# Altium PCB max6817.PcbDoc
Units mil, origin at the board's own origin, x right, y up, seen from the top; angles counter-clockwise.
Board outline 6000 x 4000 mil, 2 copper layers (Top Layer, Bottom Layer); 13 components, 8 nets, 32 pads, 2 vias.
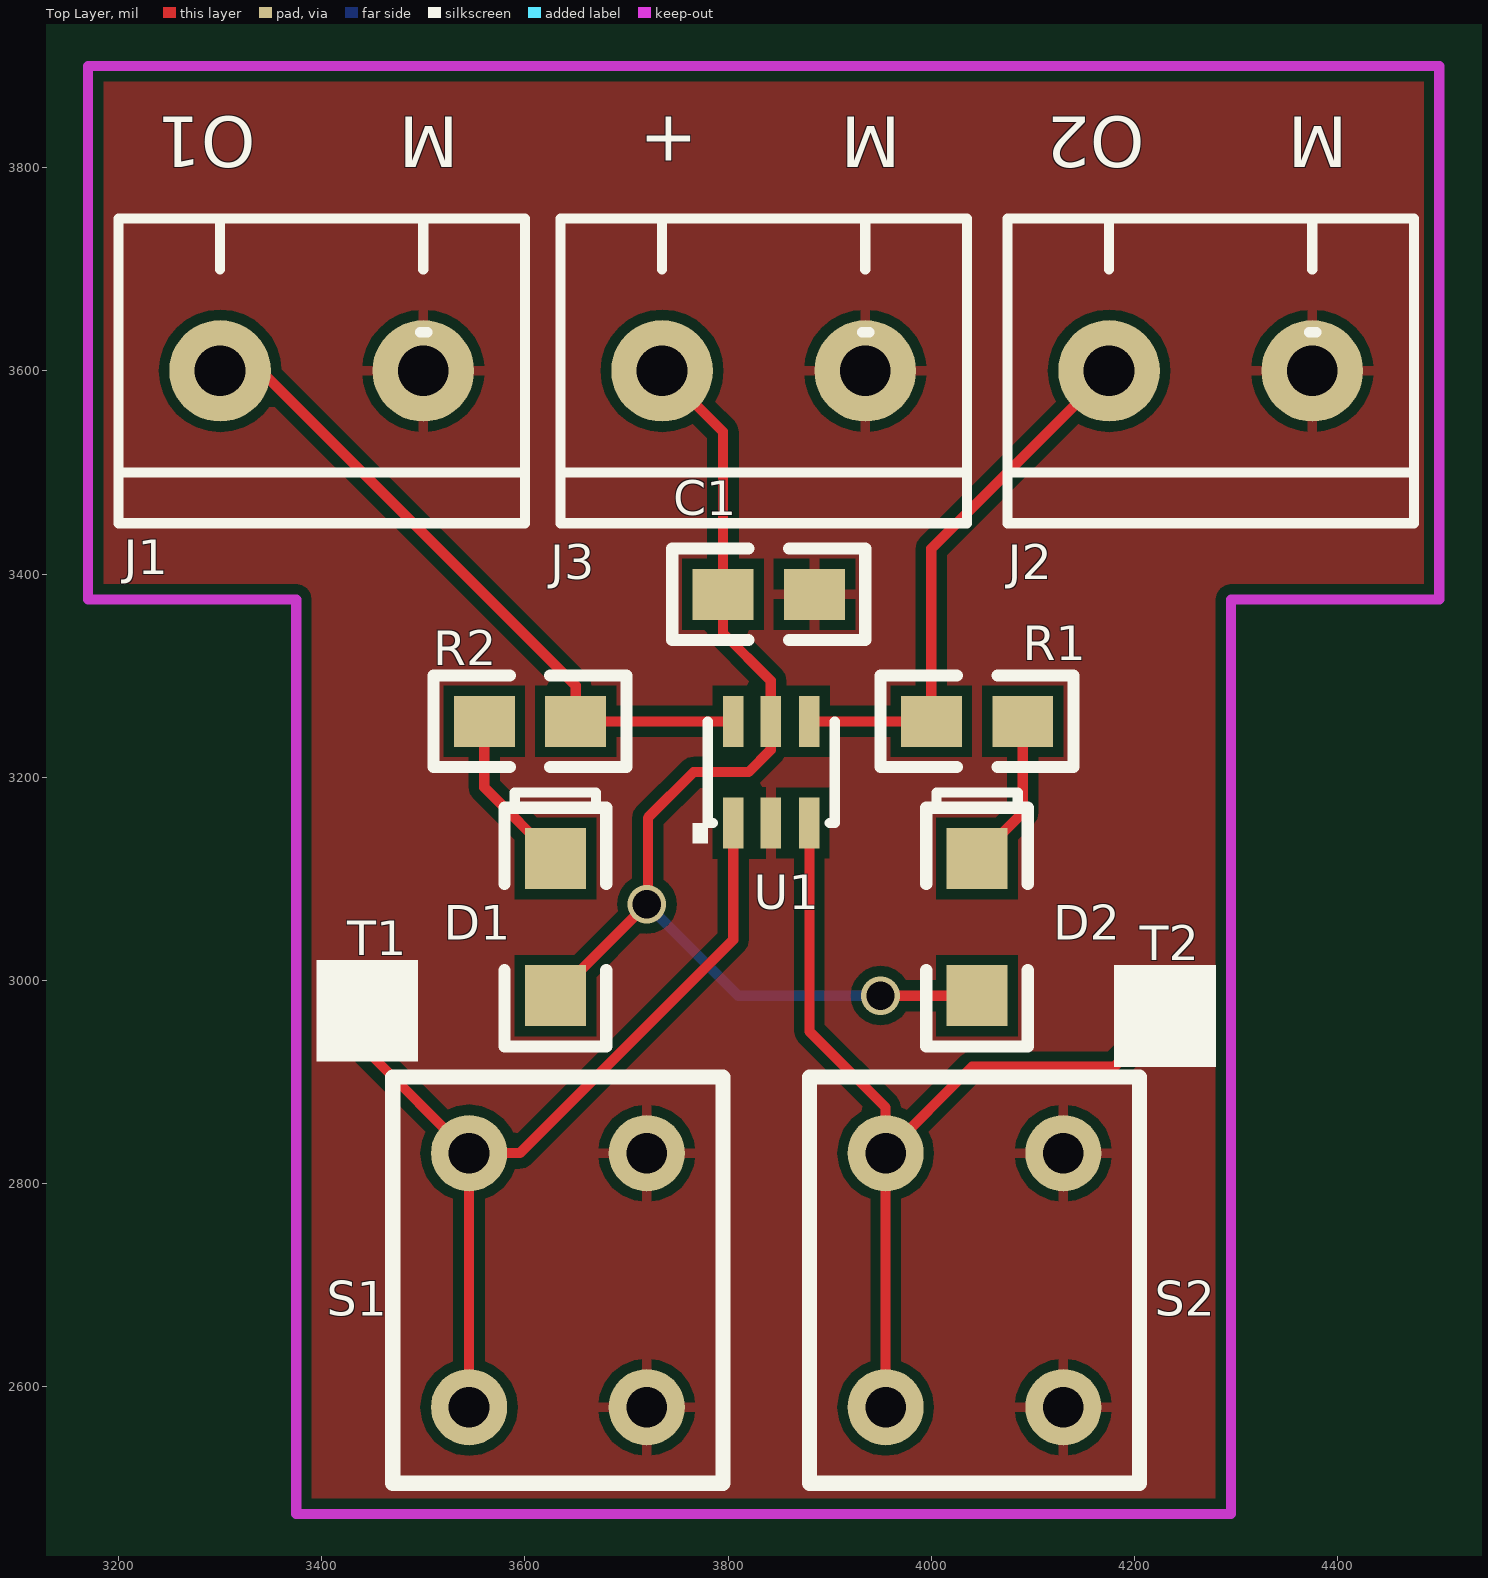
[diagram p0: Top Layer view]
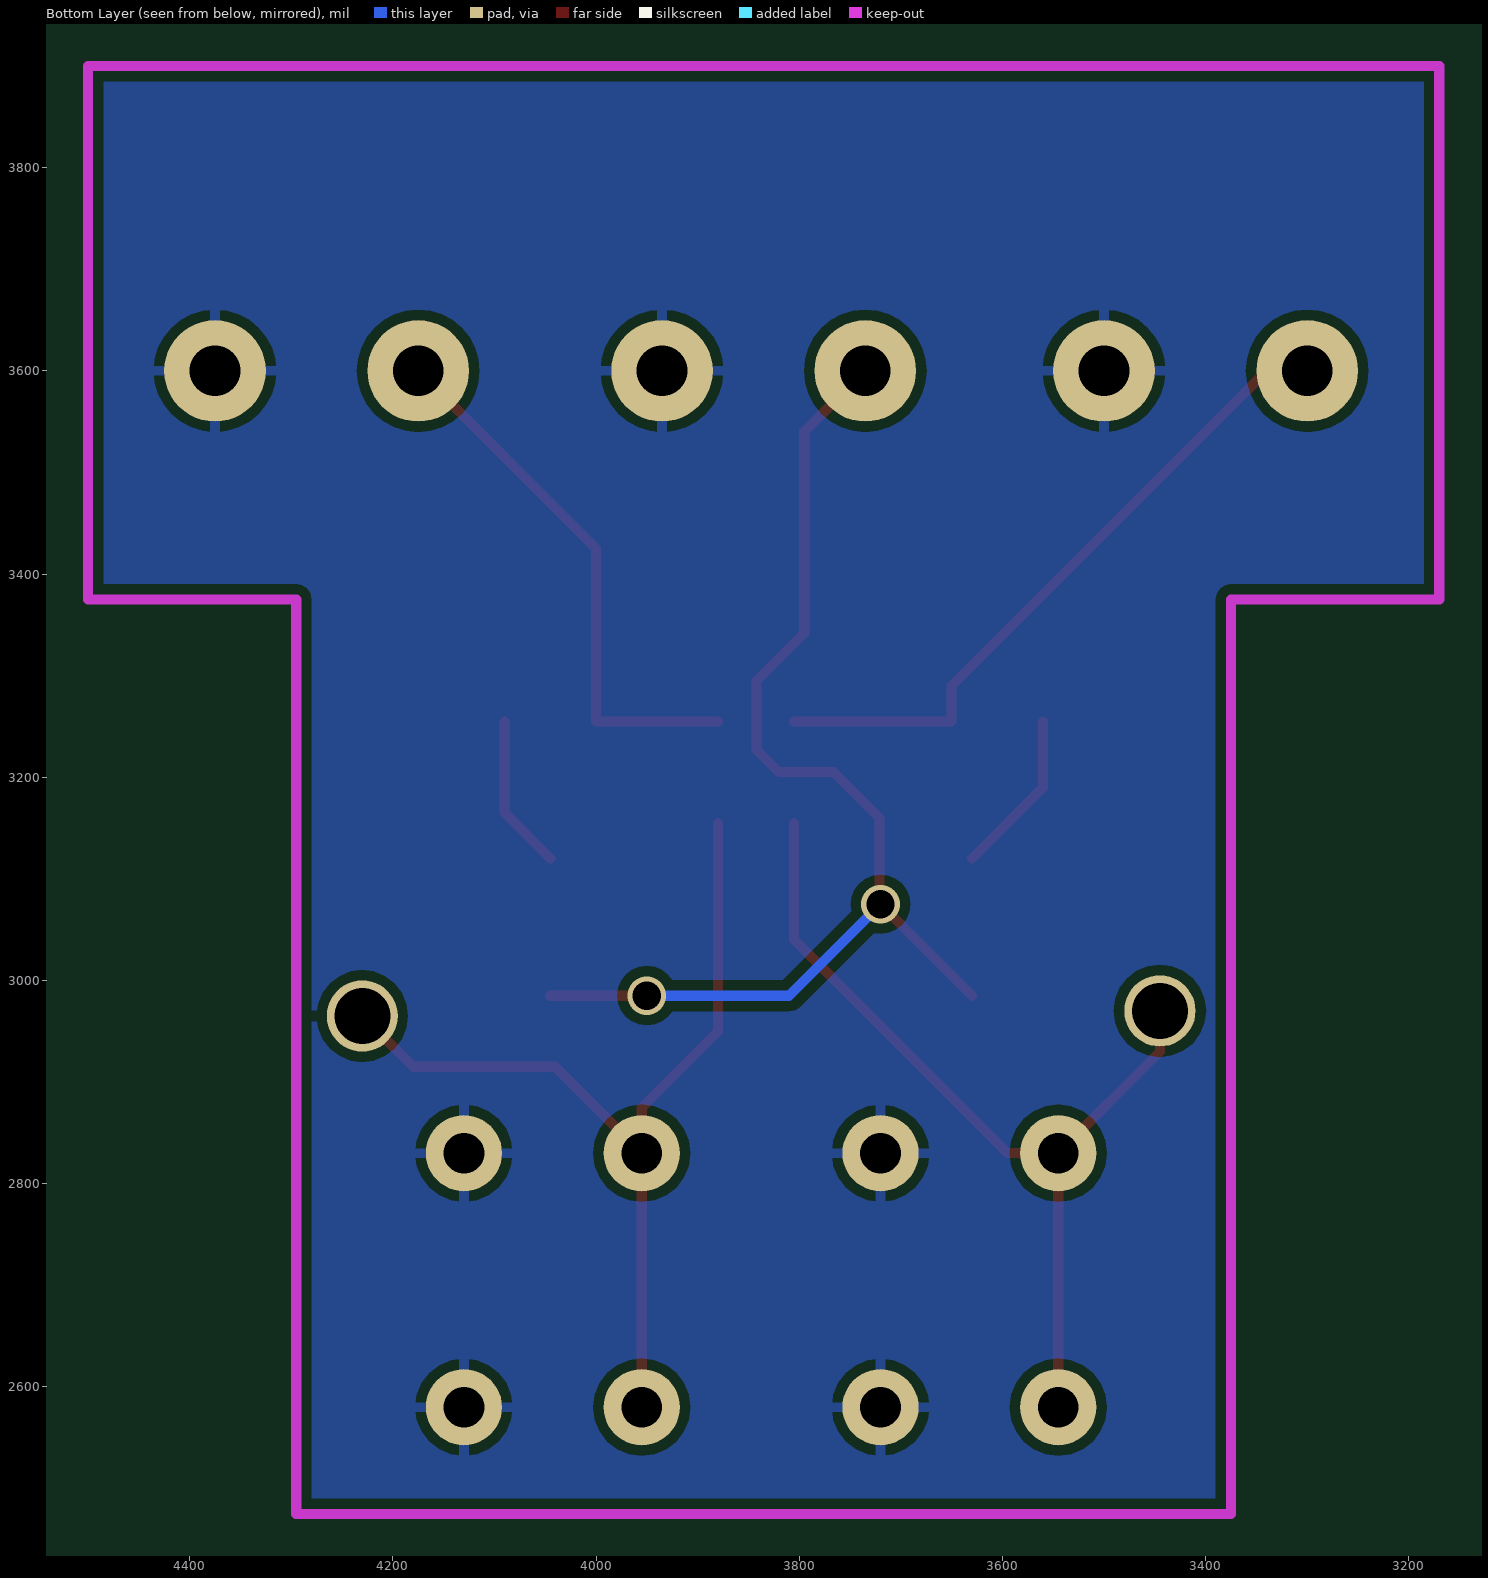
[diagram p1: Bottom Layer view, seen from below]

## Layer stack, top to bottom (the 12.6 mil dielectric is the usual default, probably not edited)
Top Layer: signal copper 1.4
Dielectric: dielectric 12.6, FR-4, Dk 4.8
Bottom Layer: signal copper 1.4

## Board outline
1000,1000 7000,1000 7000,5000 1000,5000

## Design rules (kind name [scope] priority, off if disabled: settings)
Clearance [All] p1: gap=10
PolygonConnect [All] p1: connectstyle=Relief reliefconductorwidth=10 reliefentries=4 polygonreliefangle="90 Angle"
RoutingVias [All] p1: holewidth=28 width=50 viastyle="Through Hole" minholewidth=28 minwidth=50 maxholewidth=28 maxwidth=50
SilkscreenOverComponentPads [All] p1: minsilkscreentomaskgap=10
SolderMaskExpansion [All] p1: expansion=4
Width [All] p1: maxlimit=10 minlimit=10 preferedwidth=10
27 further rules are at their usual default settings.

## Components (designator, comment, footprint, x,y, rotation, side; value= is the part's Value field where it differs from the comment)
C1 "CAP" 0805 3795,3380 r0 top
D1 "LED" 1206_LED 3630,2985 r90 top
D2 "LED" 1206_LED 4045,2985 r90 top
J1 "CON2" ARK2 3500,3600 r90 top
J2 "CON2" ARK2 4375,3600 r90 top
J3 "CON2" ARK2 3935,3600 r90 top
R1 "RES2" 0805 4000,3255 r0 top
R2 "RES2" 0805 3650,3255 r180 top
S1 "SW-PB" U_SW 3545,2830 r0 top
S2 "SW-PB" U_SW 3955,2830 r0 top
T1 "1GND" 1GND 3445,2970 r0 top
T2 "1GND" 1GND 4230,2965 r0 top
U1 "MAX6817EUT" SOT23-6 3805,3155 r180 top

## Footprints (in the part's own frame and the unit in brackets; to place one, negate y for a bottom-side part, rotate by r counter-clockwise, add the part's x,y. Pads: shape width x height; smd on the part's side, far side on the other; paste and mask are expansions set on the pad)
1GND [mil]
  round 70 hole 55: 1(0,0)
  silkscreen extent -50,-50 50,50
0805 [mil]
  rect 60x50 smd: 1(0,0) 2(90,0)
  silkscreen extent -50,-45 140,45
1206_LED [mil]
  rect 60x60 smd: 1(0,0) 2(135,0)
  silkscreen extent -50,-50 200,50
ARK2 [mil]
  round 100 hole 50: 1(0,0) 2(0,200)
  silkscreen extent -150,-100 150,300
SOT23-6 [mil]
  rect 20x50 smd: 1(0,0) 2(-37,0) 3(-75,0) 4(-75,-100) 5(-37,-100) 6(0,-100)
  silkscreen extent -100,-100 40,20
U_SW [mil]
  round 75 hole 40: 1(175,-250) 1(175,0) 2(0,-250) 2(0,0)
  silkscreen extent -75,-325 250,75

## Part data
C1: library part Cap, "Capacitor"
J1 J2 J3: "Connector"

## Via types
v1: diameter 38, hole 28, Top Layer to Bottom Layer, 2 vias

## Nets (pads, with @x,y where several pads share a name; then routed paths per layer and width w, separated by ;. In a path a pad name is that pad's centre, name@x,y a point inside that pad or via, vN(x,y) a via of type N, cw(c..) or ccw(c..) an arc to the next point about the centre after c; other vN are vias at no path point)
GND: C1.2 J1.1 J2.1 J3.1 S1.1 S2.1 U1.2
NetD1_2: D1.2 R2.2 | length 164
  Top Layer w10: R2.2 3560,3190 D1.2
NetD2_2: D2.2 R1.2 | length 153.6
  Top Layer w10: D2.2 4090,3165 R1.2
NetJ1_2: J1.2 R2.1 U1.6 | length 668.4
  Top Layer w10: J1.2 3340,3600 3650,3290 R2.1 U1.6
NetJ2_2: J2.2 R1.1 U1.4 | length 537.5
  Top Layer w10: U1.4 R1.1 4000,3425 J2.2
NetS1_2: S1.2 T1.1 U1.1 | length 893.4
  Top Layer w10: T1.1 3445,2930 S1.2@3545,2830 ; S1.2@3545,2580 S1.2@3545,2830 ; U1.1 3805,3040 3595,2830 S1.2@3545,2830
NetS2_2: S2.2 T2.1 U1.3 | length 937
  Top Layer w10: U1.3 3880,2950 3955,2875 S2.2@3955,2830 ; S2.2@3955,2580 S2.2@3955,2830 ; T2.1 4180,2915 4040,2915 S2.2@3955,2830
VCC: C1.1 D1.1 D2.1 J3.2 U1.5 | length 1141
  Top Layer w10: D1.1 v1(3720,3075) 3721,3076 3721,3160 3766,3205 3820,3205 3842,3227 U1.5 3842,3295 3795,3342 C1.1 3795,3540 J3.2 ; v1(3950,2985) D2.1
  Bottom Layer w10: v1(3720,3075) 3810,2985 v1(3950,2985)

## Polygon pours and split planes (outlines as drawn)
GND on Top Layer "Top Layer-No Net" (solid, remove dead copper, pour order 2): 3155,3915 3155,2455 3150,2450 3155,2455 4515,2455 4515,3910 3155,3910
GND on Bottom Layer "Top Layer-No Net" (solid, remove dead copper, pour order 4): 3155,3915 3155,2450 4520,2450 4520,3905 4525,3910 4520,3915 3160,3915

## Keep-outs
Keep-Out Layer:
  lines w10: 3375,2475 4295,2475 ; 3375,2475 3375,3375 3170,3375 3170,3900 4500,3900 4500,3375 4295,3375 4295,2475 ; 3375,2475 4295,2475

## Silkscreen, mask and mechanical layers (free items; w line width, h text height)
Top Overlay:
  text "O1" at 3335,3850 h50 r180
  text "M" at 3535,3850 h50 r180
  text "+" at 3770,3850 h50 r180
  text "M" at 3970,3850 h50 r180
  text "O2" at 4210,3850 h50 r180
  text "M" at 4410,3850 h50 r180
